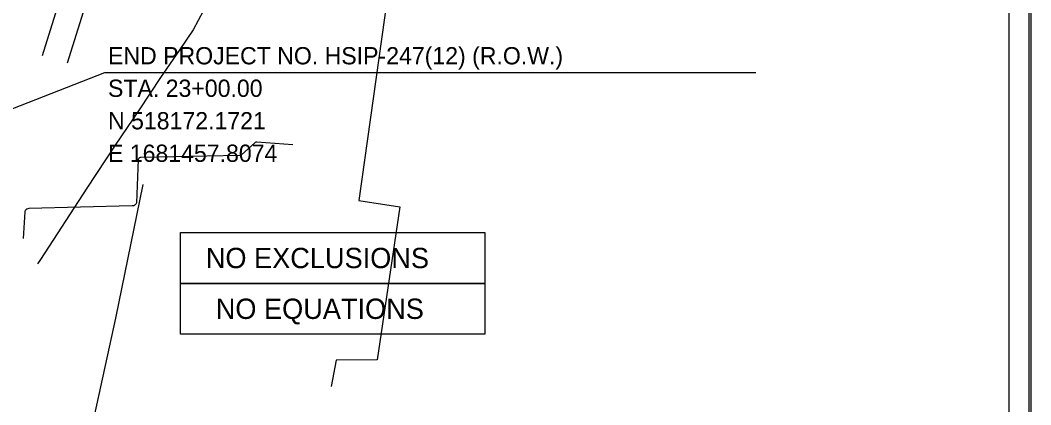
# Model space of a CAD drawing. Extents: x 1577619 to 1828281, y 483481 to 598136.
# Drawn here: x 1695627 to 1715541, y 517765 to 525338 of the extents above; entities that cross this region are included whole.
import ezdxf

# ---------------------------------------------------------------- set-up
doc = ezdxf.new("R2010")
doc.units = 0
for name, color, linetype in [('DESIGN - CENTERLINE - Proposed Text', 7, 'Continuous'), ('DESIGN - SHEET - Corner Text', 7, 'Continuous'), ('DESIGN - SHEET - Linework', 7, 'Continuous'), ('DESIGN - SHEET - Plot Shape', 7, 'Continuous'), ('SURVEY - CENTERLINE - Preliminary', 7, 'Continuous'), ('SURVEY - CENTERLINE - Preliminary Text', 7, 'Continuous'), ('SURVEY - TRANSPORTATION - Roads', 7, 'Continuous'), ('SURVEY - VEGETATION - Features with Text', 7, 'Continuous')]:
    doc.layers.add(name, color=color, linetype=linetype)

msp = doc.modelspace()

# ---------------------------------------------------------------- linework, layer by layer
at = {"layer": 'DESIGN - CENTERLINE - Proposed Text'}
for p, q in [((1681457, 518112), (1697294, 524307)), ((1697294, 524307), (1710120, 524307))]:
    msp.add_line(p, q, dxfattribs=at)
at = {"layer": 'DESIGN - SHEET - Linework'}
msp.add_line((1715541, 540205), (1715541, 496549), dxfattribs=at)
msp.add_lwpolyline([(1652139, 539377), (1715107, 539377), (1715107, 497377), (1652139, 497377), (1652139, 539377)], dxfattribs=at)
for points in [[(1698784, 521156), (1704784, 521156), (1704784, 520156), (1698784, 520156)], [(1698784, 520156), (1704784, 520156), (1704784, 519156), (1698784, 519156)]]:
    msp.add_lwpolyline(points, close=True, dxfattribs=at)
at = {"layer": 'DESIGN - SHEET - Plot Shape'}
for points in [[(1647501, 540165), (1715501, 540165), (1715501, 496589), (1647501, 496589)], [(1648737, 539377), (1715107, 539377), (1715107, 497377), (1648737, 497377)]]:
    msp.add_lwpolyline(points, close=True, dxfattribs=at)
at = {"layer": 'SURVEY - CENTERLINE - Preliminary'}
msp.add_lwpolyline([(1694013, 503946), (1694369, 505553), (1694876, 507798), (1695489, 510480), (1695992, 512706), (1696413, 514571), (1697091, 517545), (1697511, 519468), (1698047, 522105)], dxfattribs=at)
msp.add_lwpolyline([(1694013, 503946), (1694369, 505553), (1694876, 507798), (1695489, 510480), (1695992, 512706), (1696413, 514571), (1697091, 517545), (1697511, 519468), (1698047, 522105)], dxfattribs=at)
at = {"layer": 'SURVEY - CENTERLINE - Preliminary Text'}
msp.add_lwpolyline([(1699334, 525699), (1699032, 525150), (1698761, 524742), (1698390, 524208), (1697969, 523572), (1697501, 522881), (1696938, 522028), (1696025, 520623), (1695970, 520541)], dxfattribs=at)
at = {"layer": 'SURVEY - TRANSPORTATION - Roads'}
msp.add_lwpolyline([(1700996, 522883), (1700290, 522936), (1700268, 522936), (1700256, 522932), (1700248, 522927), (1699990, 522687), (1699977, 522679), (1699955, 522676), (1698006, 522635), (1697997, 522635), (1697988, 522633), (1697980, 522629), (1697974, 522625), (1697970, 522622), (1697966, 522619), (1697964, 522616), (1697958, 522608), (1697953, 522597), (1697916, 521744), (1697912, 521731), (1697907, 521719), (1697893, 521703), (1697881, 521693), (1697866, 521685), (1697848, 521681), (1697834, 521681), (1695794, 521631), (1695775, 521626), (1695756, 521617), (1695741, 521605), (1695729, 521591), (1695721, 521577), (1695715, 521563), (1695685, 521043)], dxfattribs=at)
msp.add_lwpolyline([(1700996, 522883), (1700290, 522936), (1700268, 522936), (1700256, 522932), (1700248, 522927), (1699990, 522687), (1699977, 522679), (1699955, 522676), (1698006, 522635), (1697997, 522635), (1697988, 522633), (1697980, 522629), (1697974, 522625), (1697970, 522622), (1697966, 522619), (1697964, 522616), (1697958, 522608), (1697953, 522597), (1697916, 521744), (1697912, 521731), (1697907, 521719), (1697893, 521703), (1697881, 521693), (1697866, 521685), (1697848, 521681), (1697834, 521681), (1695794, 521631), (1695775, 521626), (1695756, 521617), (1695741, 521605), (1695729, 521591), (1695721, 521577), (1695715, 521563), (1695685, 521043)], dxfattribs=at)
at = {"layer": 'SURVEY - VEGETATION - Features with Text'}
for points in [[(1698420, 531472), (1698292, 531327), (1698128, 531082), (1697954, 530697), (1696060, 524639)], [(1698420, 531472), (1698292, 531327), (1698128, 531082), (1697954, 530697), (1696060, 524639)], [(1698914, 531323), (1698786, 531179), (1698622, 530933), (1698448, 530548), (1696554, 524491)], [(1698914, 531323), (1698786, 531179), (1698622, 530933), (1698448, 530548), (1696554, 524491)], [(1703197, 528197), (1702300, 521786), (1703110, 521661), (1702660, 518651), (1701853, 518647), (1701757, 518127)], [(1703197, 528197), (1702300, 521786), (1703110, 521661), (1702660, 518651), (1701853, 518647), (1701757, 518127)]]:
    msp.add_lwpolyline(points, dxfattribs=at)

# ---------------------------------------------------------------- texts
at = {"layer": 'DESIGN - CENTERLINE - Proposed Text'}
for s, p in [('END PROJECT NO. HSIP-247(12) (R.O.W.)', (1697357, 524469)), ('STA. 23+00.00', (1697357, 523829)), ('N 518172.1721', (1697357, 523189)), ('E 1681457.8074', (1697357, 522549))]:
    msp.add_text(s, height=340, dxfattribs=at).set_placement(p)
at = {"layer": 'DESIGN - SHEET - Corner Text'}
for s, p in [('NO EXCLUSIONS', (1699284, 520456)), ('NO EQUATIONS', (1699480, 519456))]:
    msp.add_text(s, height=400, dxfattribs=at).set_placement(p)

doc.saveas('drawing.dxf')
